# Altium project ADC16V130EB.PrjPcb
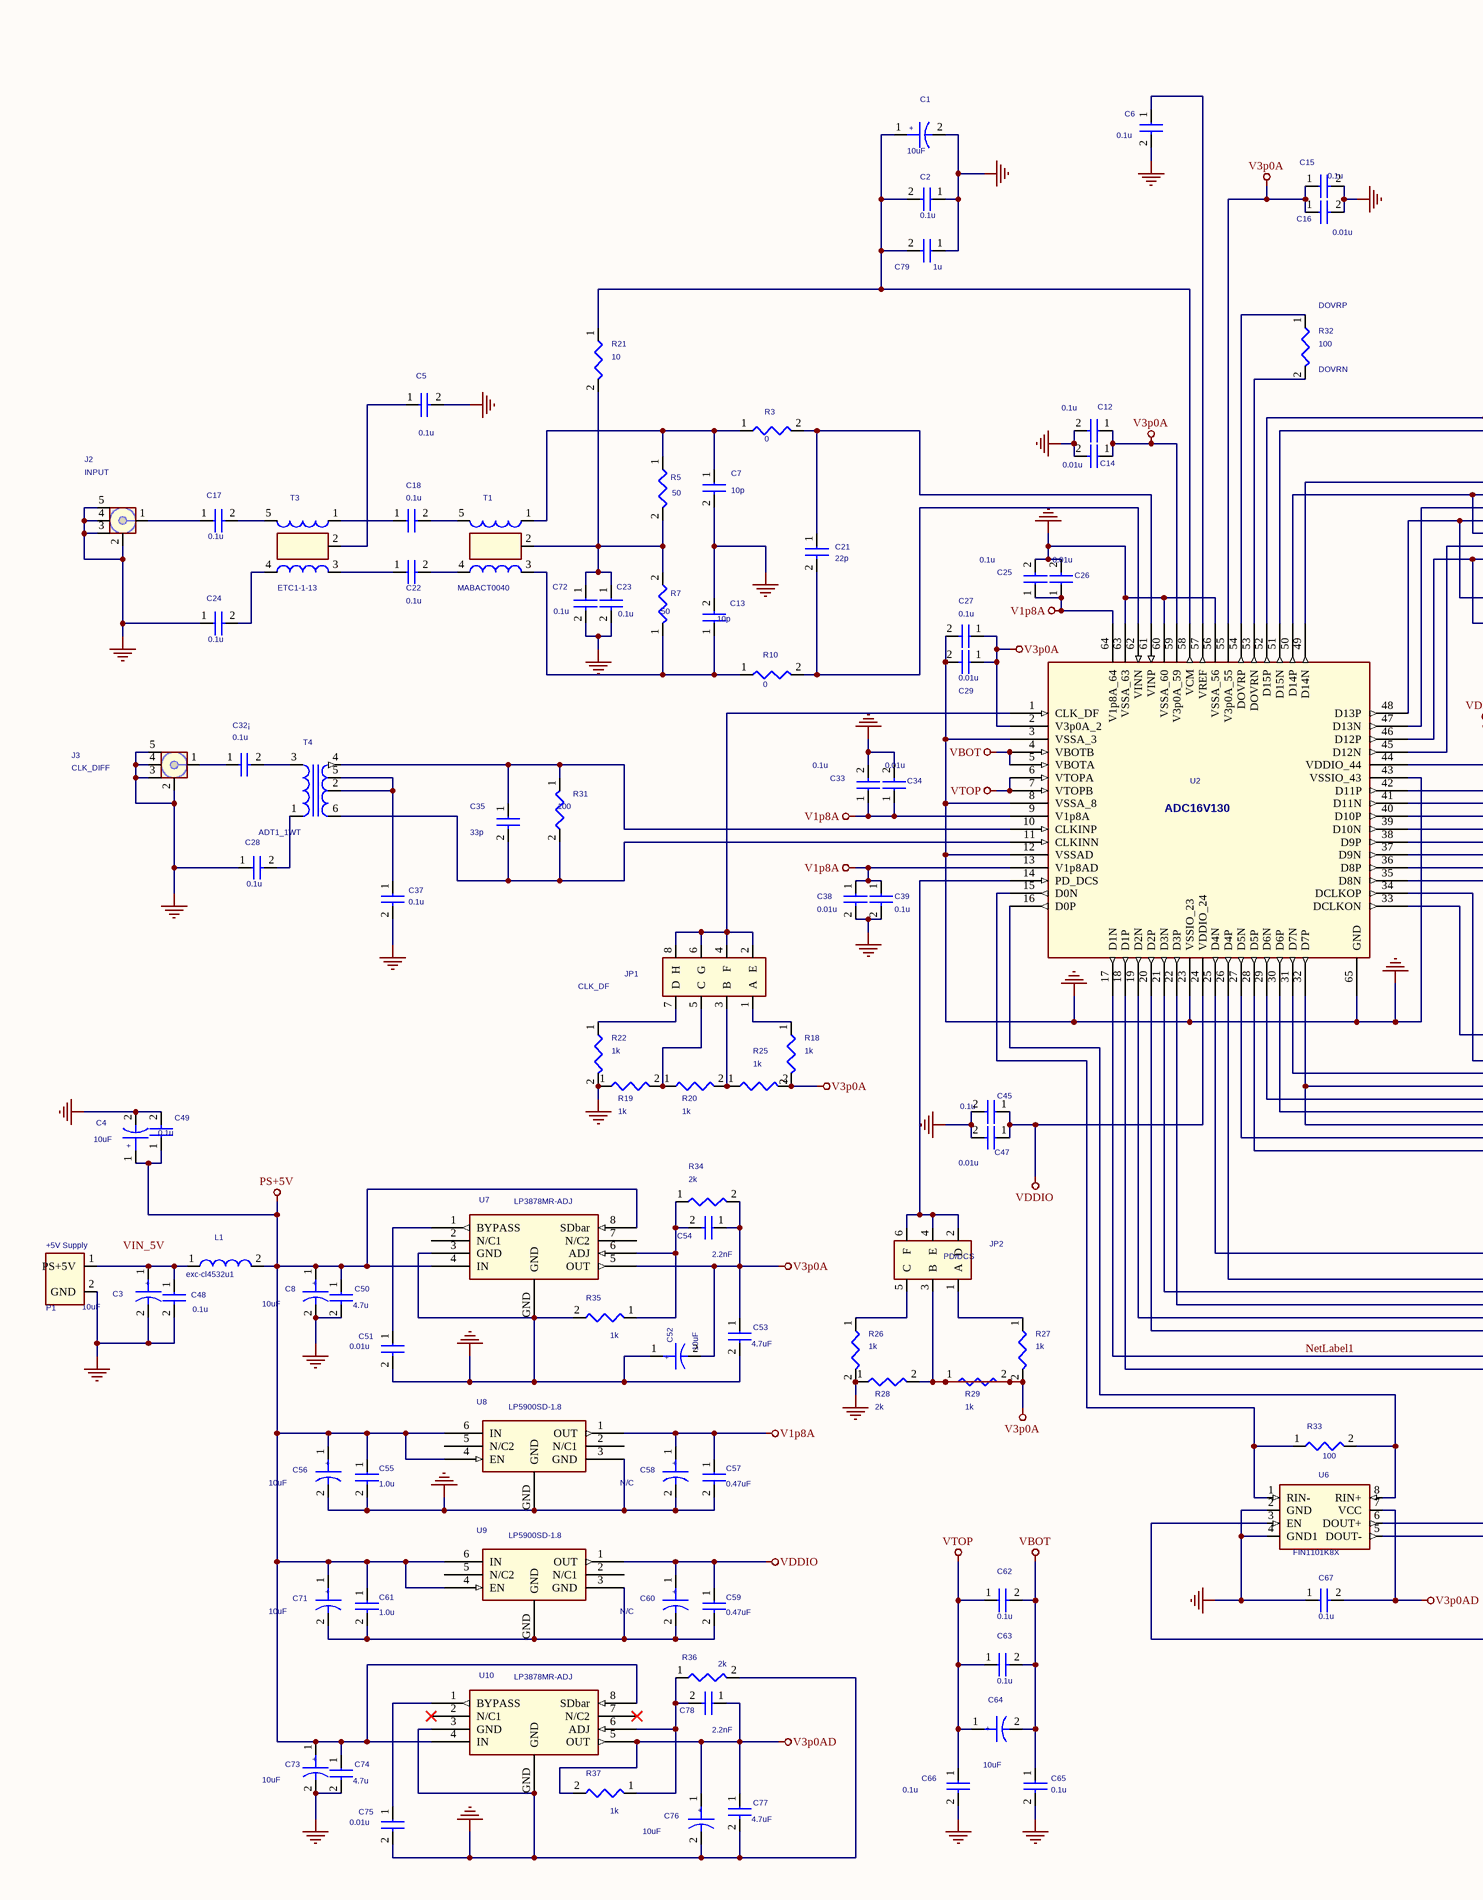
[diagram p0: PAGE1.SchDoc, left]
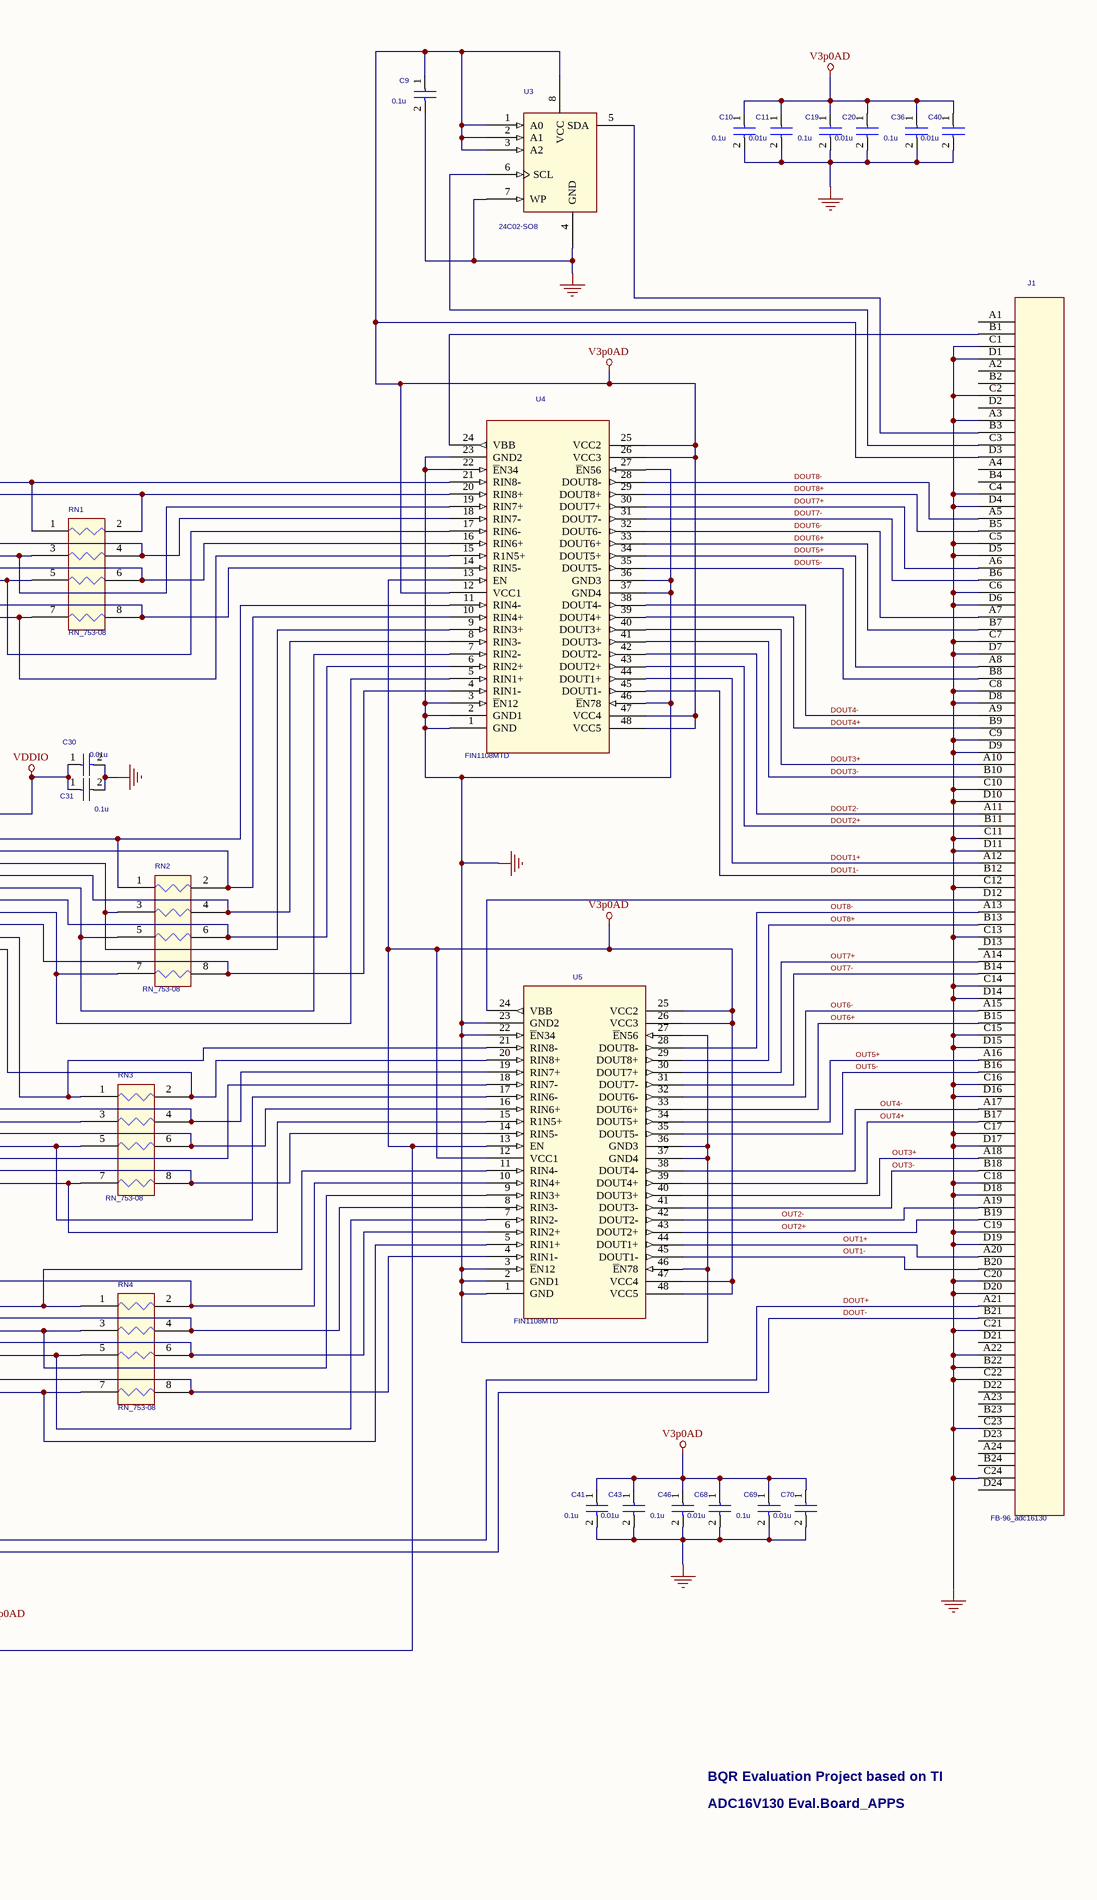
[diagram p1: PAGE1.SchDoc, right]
1 sheet, 121 parts. Net scope: global (net labels, ports and power ports of the same name join across sheets).

## Sheet PAGE1.SchDoc
size 513 x 386 mm

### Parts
C1  10uF  [cap_c-case]
C2  0.1u  [0201]
C3  10uF  [cap_c-case]
C4  10uF  [cap_c-case]
C5  0.1u  [0603]
C6  0.1u  [0402]
C7  10p  [0402]
C8  10uF  [cap_c-case]
C9  0.1u  [0603]
C10  0.1u  [0402]
C11  0.01u  [0402]
C12  0.1u  [0201]
C13  10p  [0402]
C14  0.01u  [0402]
C15  0.1u  [0201]
C16  0.01u  [0402]
C17  0.1u  [0603]
C18  0.1u  [0603]
C19  0.1u  [0402]
C20  0.01u  [0402]
C21  22p  [0402]
C22  0.1u  [0603]
C23  0.1u  [0603]
C24  0.1u  [0603]
C25  0.1u  [0201]
C26  0.01u  [0402]
C27  0.1u  [0402]
C28  0.1u  [0603]
C29  0.01u  [0402]
C30  0.01u  [0402]
C31  0.1u  [0402]
C32¡  0.1u  [0603]
C33  0.1u  [0402]
C34  0.01u  [0402]
C35  33p  [0402]
C36  0.1u  [0402]
C37  0.1u  [0603]
C38  0.01u  [0402]
C39  0.1u  [0402]
C40  0.01u  [0402]
C41  0.1u  [0402]
C43  0.01u  [0402]
C45  0.1u  [0402]
C46  0.1u  [0402]
C47  0.01u  [0402]
C48  0.1u  [0603]
C49  0.1u  [0603]
C50  4.7u  [0603]
C51  0.01u  [0603]
C52  10uF  [cap_c-case]
C53  4.7uF  [0603]
C54  2.2nF  [0603]
C55  1.0u  [0603]
C56  10uF  [cap_c-case]
C57  0.47uF  [0603]
C58  N/C  [cap_c-case]
C59  0.47uF  [0603]
C60  N/C  [cap_c-case]
C61  1.0u  [0603]
C62  0.1u  [0402]
C63  0.1u  [0402]
C64  10uF  [cap_a-case]
C65  0.1u  [0402]
C66  0.1u  [0402]
C67  0.1u  [0402]
C68  0.01u  [0402]
C69  0.1u  [0402]
C70  0.01u  [0402]
C71  10uF  [cap_c-case]
C72  0.1u  [0402]
C73  10uF  [cap_c-case]
C74  4.7u  [0603]
C75  0.01u  [0603]
C76  10uF  [cap_c-case]
C77  4.7uF  [0603]
C78  2.2nF  [0603]
C79  1u  [0508]
J1  FB-96_adc16130  [con96-fb_16130]
J2  INPUT  [RFSMAVCLRJ8]
J3  CLK_DIFF  [RFSMAVCLRJ8]
JP1  CLK_DF  [hdr-2x4-100]
JP2  PD/DCS  [hdr-2x3-100]
L1  exc-cl4532u1  [exc-cl4532u1]
P1  +5V Supply  [tb-2pos_plug]
R3  0  [0402]
R5  50  [0402]
R7  50  [0402]
R10  0  [0402]
R18  1k  [0603]
R19  1k  [0603]
R20  1k  [0603]
R21  10  [0603]
R22  1k  [0603]
R25  1k  [0603]
R26  1k  [0603]
R27  1k  [0603]
R28  2k  [0603]
R29  1k  [0603]
R31  100  [0402]
R32  100  [0402]
R33  100  [0402]
R34  2k  [0603]
R35  1k  [0603]
R36  2k  [0603]
R37  1k  [0603]
RN1  RN_753-08  [753083101gtr]
RN2  RN_753-08  [753083101gtr]
RN3  RN_753-08  [753083101gtr]
RN4  RN_753-08  [753083101gtr]
T1  MABACT0040  [etc1-1-13]
T3  ETC1-1-13  [etc1-1-13]
T4  ADT1_1WT  [ADT1]
U2  ADC16V130  [llp64_16130_no-skt]
U3  24C02-SO8  [soic8_150amps]
U4  FIN1108MTD  [tssop48_fin1108mtd]
U5  FIN1108MTD  [tssop48_fin1108mtd]
U6  FIN1101K8X  [us8_fin1101k8x]
U7  LP3878MR-ADJ  [lp3878-adj_mra08a-psop]
U8  LP5900SD-1.8  [lp5900_sdb06a-llp6]
U9  LP5900SD-1.8  [lp5900_sdb06a-llp6]
U10  LP3878MR-ADJ  [lp3878-adj_mra08a-psop]

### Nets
GND: C1.2 C2.1 C3.2 C4.2 C5.2 C6.2 C7.2 C8.2 C9.2 C10.2 C11.2 C12.2 C13.2 C14.2 C15.2 C16.2 C19.2 C20.2 C23.2 C24.1 C25.2 C26.2 C27.2 C28.1 C29.2 C30.2 C31.2 C33.2 C34.2 C36.2 C37.2 C38.2 C39.2 C40.2 C41.2 C43.2 C45.2 C46.2 C47.2 C48.2 C49.2 C50.2 C51.2 C52.1 C53.2 C55.2 C56.2 C57.2 C58.2 C65.2 C66.2 C67.1 C68.2 C69.2 C70.2 C72.2 C73.2 C74.2 C75.2 C76.2 C77.2 C79.1 J1.A3 J1.A22 J1.B22 J1.C1 J1.C2 J1.C4 J1.C5 J1.C6 J1.C7 J1.C8 J1.C9 J1.C10 J1.C11 J1.C12 J1.C13 J1.C14 J1.C15 J1.C16 J1.C17 J1.C18 J1.C19 J1.C20 J1.C21 J1.C22 J1.C23 J1.C24 J1.D1 J1.D4 J1.D5 J1.D6 J1.D7 J1.D8 J1.D9 J1.D10 J1.D11 J1.D14 J1.D15 J1.D16 J1.D17 J1.D18 J1.D19 J1.D20 J2.2(SHIELD2) J2.3(SHIELD3) J2.4(SHIELD4) J2.5(SHIELD5) J3.2(SHIELD2) J3.3(SHIELD3) J3.4(SHIELD4) J3.5(SHIELD5) P1.2(GND) R19.1 R22.2 R26.2 R28.1 R35.2 R36.2 U2.3(VSSA_3) U2.8(VSSA_8) U2.12(VSSAD) U2.23(VSSIO_23) U2.43(VSSIO_43) U2.56(VSSA_56) U2.60(VSSA_60) U2.63(VSSA_63) U2.65(GND) U3.4(GND) U3.7(WP) U4.1(GND) U4.2(GND1) U4.3(~{E}N12) U4.22(~{E}N34) U4.23(GND2) U4.27(~{E}N56) U4.36(GND3) U4.37(GND4) U4.46(~{E}N78) U5.1(GND) U5.2(GND1) U5.3(~{E}N12) U5.22(~{E}N34) U5.23(GND2) U5.27(~{E}N56) U5.36(GND3) U5.37(GND4) U5.46(~{E}N78) U6.2(GND) U6.4(GND1) U7.3(GND) U7.GND U8.3(GND) U8.GND U10.3(GND) U10.GND
PS+5V: C4.1 C8.1 C49.1 C50.1 C55.1 C56.1 C61.1 C71.1 C73.1 C74.1 L1.2 U7.4(IN) U7.8(SDbar) U8.4(EN) U8.6(IN) U9.4(EN) U9.6(IN) U10.4(IN) U10.8(SDbar)
V1p8A: C25.1 C26.1 C33.1 C34.1 C38.1 C39.1 C57.1 C58.1 U2.9(V1p8A) U2.13(V1p8AD) U2.64(V1p8A_64) U8.1(OUT)
V3p0A: C12.1 C14.1 C15.1 C16.1 C27.1 C29.1 C52.2 C53.1 C54.1 JP2.3(B) R18.2 R25.2 R27.2 R28.2 R29.1 R29.2 R34.2 U2.2(V3p0A_2) U2.55(V3p0A_55) U2.59(V3p0A_59) U7.5(OUT)
V3p0AD: C9.1 C10.1 C11.1 C19.1 C20.1 C36.1 C40.1 C41.1 C43.1 C46.1 C67.2 C68.1 C69.1 C70.1 C76.1 C77.1 C78.1 J1.D3 R37.2 U3.1(A0) U3.2(A1) U3.3(A2) U3.8(VCC) U4.12(VCC1) U4.13(EN) U4.25(VCC2) U4.26(VCC3) U4.47(VCC4) U4.48(VCC5) U5.12(VCC1) U5.13(EN) U5.25(VCC2) U5.26(VCC3) U5.47(VCC4) U5.48(VCC5) U6.3(EN) U6.7(VCC) U10.5(OUT)
VBOT: C62.2 C63.2 C64.2 C65.1 U2.4(VBOTB) U2.5(VBOTA)
VDDIO: C30.1 C31.1 C45.1 C47.1 C59.1 C60.1 U2.24(VDDIO_24) U2.44(VDDIO_44) U9.1(OUT)
VTOP: C62.1 C63.1 C64.1 C66.1 U2.6(VTOPA) U2.7(VTOPB)
DOUT1+: J1.A12 U4.44(DOUT1+)
DOUT1-: J1.B12 U4.45(DOUT1-)
DOUT2+: J1.B11 U4.43(DOUT2+)
DOUT2-: J1.A11 U4.42(DOUT2-)
DOUT3+: J1.A10 U4.40(DOUT3+)
DOUT3-: J1.B10 U4.41(DOUT3-)
DOUT4+: J1.B9 U4.39(DOUT4+)
DOUT4-: J1.A9 U4.38(DOUT4-)
DOUT5+: J1.A8 U4.34(DOUT5+)
DOUT5-: J1.B8 U4.35(DOUT5-)
DOUT6+: J1.B7 U4.33(DOUT6+)
DOUT6-: J1.A7 U4.32(DOUT6-)
DOUT7+: J1.A6 U4.30(DOUT7+)
DOUT7-: J1.B6 U4.31(DOUT7-)
DOUT8+: J1.B5 U4.29(DOUT8+)
DOUT8-: J1.A5 U4.28(DOUT8-)
DOUT+: J1.A21 U6.6(DOUT+)
DOUT-: J1.B21 U6.5(DOUT-)
NetLabel1: RN4.8 U2.17(D1N) U5.4(RIN1-)
OUT1+: J1.A20 U5.44(DOUT1+)
OUT1-: J1.B20 U5.45(DOUT1-)
OUT2+: J1.B19 U5.43(DOUT2+)
OUT2-: J1.A19 U5.42(DOUT2-)
OUT3+: J1.A18 U5.40(DOUT3+)
OUT3-: J1.B18 U5.41(DOUT3-)
OUT4+: J1.B17 U5.39(DOUT4+)
OUT4-: J1.A17 U5.38(DOUT4-)
OUT5+: J1.A16 U5.34(DOUT5+)
OUT5-: J1.B16 U5.35(DOUT5-)
OUT6+: J1.B15 U5.33(DOUT6+)
OUT6-: J1.A15 U5.32(DOUT6-)
OUT7+: J1.A14 U5.30(DOUT7+)
OUT7-: J1.B14 U5.31(DOUT7-)
OUT8+: J1.B13 U5.29(DOUT8+)
OUT8-: J1.A13 U5.28(DOUT8-)
NetC1_1: C1.1 C2.2 C79.2 R21.1 U2.58(VCM)
NetC3_1: C3.1 C48.1 L1.1 P1.1(PS+5V)
NetC5_1: C5.1 T3.2
NetC6_1: C6.1 U2.57(VREF)
NetC7_1: C7.1 R3.1 R5.1 T1.1
NetC13_1: C13.1 R7.1 R10.1 T1.3
NetC17_1: C17.1 J2.1(CENTER)
NetC17_2: C17.2 T3.5
NetC18_1: C18.1 T3.1
NetC18_2: C18.2 T1.5
NetC21_1: C21.1 R3.2 U2.61(VINP)
NetC21_2: C21.2 R10.2 U2.62(VINN)
NetC22_1: C22.1 T3.3
NetC22_2: C22.2 T1.4
NetC23_1: C23.1 C72.1 R5.2 R7.2 R21.2 T1.2
NetC24_2: C24.2 T3.4
NetC28_2: C28.2 T4.1
NetC32¡_1: C32¡.1 J3.1(CENTER)
NetC32¡_2: C32¡.2 T4.3
NetC35_1: C35.1 R31.1 T4.4 U2.10(CLKINP)
NetC35_2: C35.2 R31.2 T4.6 U2.11(CLKINN)
NetC37_1: C37.1 T4.2 T4.5
NetC51_1: C51.1 U7.1(BYPASS)
NetC54_2: C54.2 R34.1 R35.1 U7.6(ADJ)
NetC59_2: C59.2 C60.2 C61.2 C71.2 U9.3(GND) U9.GND
NetC75_1: C75.1 U10.1(BYPASS)
NetC78_2: C78.2 R36.1 R37.1 U10.6(ADJ)
NetJ1_B1: J1.B1 U4.24(VBB)
NetJ1_B3: J1.B3 U3.5(SDA)
NetJ1_C3: J1.C3 U3.6(SCL)
NetJ1_D12: J1.D12 U5.24(VBB)
NetJP1_1: JP1.1(A) R18.1
NetJP1_2: JP1.2(E) JP1.4(F) JP1.6(G) JP1.8(H) U2.1(CLK_DF)
NetJP1_3: JP1.3(B) R20.2 R25.1
NetJP1_5: JP1.5(C) R19.2 R20.1
NetJP1_7: JP1.7(D) R22.1
NetJP2_1: JP2.1(A) R27.1
NetJP2_2: JP2.2(D) JP2.4(E) JP2.6(F) U2.14(PD_DCS)
NetJP2_5: JP2.5(C) R26.1
NetR32_1: R32.1 U2.54(DOVRP)
NetR32_2: R32.2 U2.53(DOVRN)
NetR33_1: R33.1 U2.15(D0N) U6.1(RIN-)
NetR33_2: R33.2 U2.16(D0P) U6.8(RIN+)
NetRN1_1: RN1.1 U2.52(D15P) U4.21(RIN8-)
NetRN1_2: RN1.2 U2.51(D15N) U4.20(RIN8+)
NetRN1_3: RN1.3 U2.50(D14P) U4.19(RIN7+)
NetRN1_4: RN1.4 U2.49(D14N) U4.18(RIN7-)
NetRN1_5: RN1.5 U2.48(D13P) U4.17(RIN6-)
NetRN1_6: RN1.6 U2.47(D13N) U4.16(RIN6+)
NetRN1_7: RN1.7 U2.46(D12P) U4.15(R1N5+)
NetRN1_8: RN1.8 U2.45(D12N) U4.14(RIN5-)
NetRN2_1: RN2.1 U2.42(D11P) U4.11(RIN4-)
NetRN2_2: RN2.2 U2.41(D11N) U4.10(RIN4+)
NetRN2_3: RN2.3 U2.40(D10P) U4.9(RIN3+)
NetRN2_4: RN2.4 U2.39(D10N) U4.8(RIN3-)
NetRN2_5: RN2.5 U2.38(D9P) U4.7(RIN2-)
NetRN2_6: RN2.6 U2.37(D9N) U4.6(RIN2+)
NetRN2_7: RN2.7 U2.36(D8P) U4.5(RIN1+)
NetRN2_8: RN2.8 U2.35(D8N) U4.4(RIN1-)
NetRN3_1: RN3.1 U2.34(DCLKOP) U5.21(RIN8-)
NetRN3_2: RN3.2 U2.33(DCLKON) U5.20(RIN8+)
NetRN3_3: RN3.3 U2.32(D7P) U5.18(RIN7-)
NetRN3_4: RN3.4 U2.31(D7N) U5.19(RIN7+)
NetRN3_5: RN3.5 U2.30(D6P) U5.17(RIN6-)
NetRN3_6: RN3.6 U2.29(D6N) U5.16(RIN6+)
NetRN3_7: RN3.7 U2.28(D5P) U5.15(R1N5+)
NetRN3_8: RN3.8 U2.27(D5N) U5.14(RIN5-)
NetRN4_1: RN4.1 U2.26(D4P) U5.11(RIN4-)
NetRN4_2: RN4.2 U2.25(D4N) U5.10(RIN4+)
NetRN4_3: RN4.3 U2.22(D3P) U5.9(RIN3+)
NetRN4_4: RN4.4 U2.21(D3N) U5.8(RIN3-)
NetRN4_5: RN4.5 U2.20(D2P) U5.7(RIN2-)
NetRN4_6: RN4.6 U2.19(D2N) U5.6(RIN2+)
NetRN4_7: RN4.7 U2.18(D1P) U5.5(RIN1+)

Not connected (* = marked no-connect by the designer): J1 A1(1) A2(5) A4(13) A23(89) A24(93) B2(6) B4(14) B23(90) B24(94) D2(8) D13(52) D21(84) D22(88) D23(92) D24(96); U7 2(N/C1) 7(N/C2); U8 2(N/C1) 5(N/C2); U9 2(N/C1) 5(N/C2); U10 2(N/C1)* 7(N/C2)*

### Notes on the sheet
- (near R32) DOVRP
- (near R32) DOVRN
- BQR Evaluation Project based on TI
- ADC16V130 Eval.Board_APPS
- Labels drawn without touching a wire or pin: VIN_5V

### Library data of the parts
C1 C4 C8 C52 C56 C58 C60 C71 C73 = Cap_Polar_1: CAP TANT 10UF 20V 10% 2312; Manufacturer P/N: TAJC106K020R; Manufacturer: AVX; Catalog Number: CAP00001
C2 = Capacitor_4: CAP CER 0.1UF 6.3V X5R 0201; Manufacturer P/N: GRM033R60J104KE19D; Manufacturer: Murata; Catalog Number: CAP00002
C3 = Cap_Polar_1: CAP TANT 10UF 6.3V 10% 1206; Manufacturer: AVX_1; Manufacturer P/N: TAJA106K006R; Catalog Number: CAP00039
C5 C17 C18 C22-C24 C28 C32¡ C37 = Capacitor_4: CAP CER 0.1UF 16V X7R 0603; Manufacturer: Murata; Manufacturer P/N: GRM188R71C104KA01D; Catalog Number: CAP00036
C6 C65 C66 C72 = Capacitor_4: CAP CER 0.1UF 10V X5R 0402; Manufacturer P/N: GRM155R61A104KA01D; Manufacturer: Murata; Catalog Number: CAP00026
C7 = Capacitor_4: CAP CER 10PF 50V NP0 0402; Manufacturer: Murata; Manufacturer P/N: GRM1555C1H100JZ01D; Catalog Number: CAP00029
C9 = Capacitor_4: CAP CER 0.1UF 16V X7R 0603; Manufacturer: Murata; Manufacturer P/N: GRM188R71C104KA01D; Catalog Number: CAP00036; SDTA_V(Voltage): 3
C10 C19 C36 C41 C46 C69 = Capacitor_4: CAP CER 0.1UF 10V X5R 0402; Manufacturer P/N: GRM155R61A104KA01D; Manufacturer: Murata; Catalog Number: CAP00026; SDTA_V(Voltage): 3
C11 C20 C40 C43 C68 C70 = Capacitor_4: CAP CER 10000PF 50V X7R 0402; Manufacturer P/N: GRM155R71H103KA88D; Manufacturer: Murata; Catalog Number: CAP00027; SDTA_V(Voltage): 3
C12 C15 C25 = Cap_1: CAP CER 0.1UF 6.3V X5R 0201; Manufacturer P/N: GRM033R60J104KE19D; Manufacturer: Murata; Catalog Number: CAP00002
C13 = Capacitor_4: CAP CER 10PF 50V NP0 0402; Manufacturer P/N: GRM1555C1H100JZ01D; Manufacturer: Murata; Catalog Number: CAP00029
C14 C16 C26 C29 C30 C34 C38 C47 = Cap_1: CAP CER 10000PF 50V X7R 0402; Manufacturer P/N: GRM155R71H103KA88D; Manufacturer: Murata; Catalog Number: CAP00027
C21 = Capacitor_4: CAP CER 22PF 50V NP0 0402; Manufacturer P/N: GRM1555C1H220JZ01D; Manufacturer: Murata; Catalog Number: CAP00037
C27 C31 C33 C39 C45 = Cap_1: CAP CER 0.1UF 10V X5R 0402; Manufacturer P/N: GRM155R61A104KA01D; Manufacturer: Murata; Catalog Number: CAP00026
C35 = Capacitor_3: CAP CER 33PF 50V NP0 0402; Manufacturer: Murata; Manufacturer P/N: GRM1555C1H330JZ01D; Catalog Number: CAP00038
C48 C49 = Capacitor_3: CAP CER 0.1UF 16V X7R 0603; Manufacturer: Murata; Manufacturer P/N: GRM188R71C104KA01D; Catalog Number: CAP00036
C50 = Capacitor_3: CAP CER 4.7UF 6.3V X5R 0603; Manufacturer: Panasonic; Manufacturer P/N: ECJ-1VB0J475M; Catalog Number: CAP00017
C51 C75 = Capacitor_3: CAP CER 10000PF 50V X7R 0603; Manufacturer P/N: ECJ-1VB1H103K; Manufacturer: Panasonic; Catalog Number: CAP00018
C53 C74 = Capacitor_3: CAP CER 4.7UF 6.3V X5R 0603; Manufacturer P/N: ECJ-1VB0J475M; Manufacturer: Panasonic; Catalog Number: CAP00017
C54 C78 = Cap_1: CAP CER 2200PF 50V X7R 0603; Manufacturer P/N: ECJ-1VB1H222K; Manufacturer: Panasonic; Catalog Number: CAP00019
C55 = Capacitor_3: CAP CER 1UF 16V X7R 0603; Manufacturer: Murata; Manufacturer P/N: GRM188R71C105KA12D; Catalog Number: CAP00028
C57 C59 = Capacitor_3: CAP CER 0.47UF 6.3V X5R 0603; Manufacturer P/N: ECJ-1VB0J474K; Manufacturer: Panasonic; Catalog Number: CAP00016
C61 = Capacitor_3: CAP CER 1UF 16V X7R 0603; Manufacturer P/N: GRM188R71C105KA12D; Manufacturer: Murata; Catalog Number: CAP00028
C62 C63 = Capacitor_3: CAP CER 0.1UF 10V X5R 0402; Manufacturer P/N: GRM155R61A104KA01D; Manufacturer: Murata; Catalog Number: CAP00026
C64 = Cap_Polar_1: CAP TANT 10UF 10V 20% 1206; Manufacturer P/N: F931A106MAA; Manufacturer: Nichicon; Catalog Number: CAP00023
C67 = Cap_1: CAP CER 0.1UF 10V X5R 0402; Manufacturer P/N: GRM155R61A104KA01D; Manufacturer: Murata; Catalog Number: CAP00026; SDTA_V(Voltage): 3
C76 = Cap_Polar_1: CAP TANT 10UF 20V 10% 2312; Manufacturer P/N: TAJC106K020R; Manufacturer: AVX; Catalog Number: CAP00001; SDTA_V(Voltage): 3
C77 = Capacitor_3: CAP CER 4.7UF 6.3V X5R 0603; Manufacturer: Panasonic; Manufacturer P/N: ECJ-1VB0J475M; Catalog Number: CAP00017; SDTA_V(Voltage): 3
C79 = Capacitor_4: CAP CER 1UF 10V X5R 0508; Manufacturer P/N: ECY-29RA105KV; Manufacturer: Panasonic; Catalog Number: CAP00020
J1 = CON-FB96-ADC16130: 2MM FB,IS,ASY,024,SIG,HDR,SL; Manufacturer: AMP/Tyco; Manufacturer P/N: 223514-1; Catalog Number: CON00005
J2 = SMA_CONN_4: SMA Connector Jack, Female Socket 50 Ohm Board Edge, End Launch Solder Tab; Manufacturer: JOHNSON; Manufacturer P/N: 142-0701-851; Catalog Number: CON00004
J3 = SMA_CONN_5: SMA Connector Jack, Female Socket 50 Ohm Board Edge, End Launch Solder Tab; Manufacturer P/N: 142-0701-851; Manufacturer: JOHNSON; Catalog Number: CON00004
JP1 = HDR-2x4_0: 8 Positions Header, Unshrouded Connector 0.100" (2.54mm) Through Hole Gold; Manufacturer P/N: TSW-104-07-F-D; Manufacturer: Samtec; Catalog Number: CON00035
JP2 = HDR-2x3: 6 Positions Header, Unshrouded Connector 0.100" (2.54mm) Through Hole Gold; Manufacturer P/N: TSW-103-07-F-D; Manufacturer: Samtec; Catalog Number: CON00034
L1 = Inductor: FERRITE BEAD 115 OHM 1812 1LN; Manufacturer: Panasonic; Catalog Number: IND00022
P1 = TB2_1: CONN RCPT SUR 2POS .8MM TIN; Manufacturer P/N: 02SUR-32S; Manufacturer: JST; Catalog Number: CON00003
R3 R10 = Resistor_3: RES SMD 0.0OHM JUMPER 1/16W 0402; Manufacturer: Vishay; Manufacturer P/N: CRCW04020000Z0ED; Catalog Number: RES00015
R5 R7 = Resistor_3: RES SMD 49.9 OHM 1% 1/16W 0402; Manufacturer P/N: CRCW040249R9FKED; Manufacturer: Vishay; Catalog Number: RES00012
R18-R20 R22 R25-R27 R29 R35 R37 = Resistor_3: RES SMD 1K OHM 1% 1/10W 0603; Manufacturer P/N: CRCW06031K00FKEA; Manufacturer: Vishay; Catalog Number: RES00010
R21 = Resistor_3: RES SMD 10 OHM 1% 1/10W 0603; Manufacturer P/N: CRCW060310R0FKEA; Manufacturer: Vishay; Catalog Number: RES00013
R28 R34 R36 = Resistor_3: RES SMD 2K OHM 1% 1/10W 0603; Manufacturer P/N: CRCW06032K00FKEA; Manufacturer: Vishay; Catalog Number: RES00011
R31 R33 = Resistor_3: RES SMD 100 OHM 1% 1/16W 0402; Manufacturer P/N: CRCW0402100RFKED; Manufacturer: Vishay; Catalog Number: RES00014
R32 = Resistor_3: RES SMD 100 OHM 1% 1/16W 0402; Manufacturer: Vishay; Manufacturer P/N: CRCW0402100RFKED; Catalog Number: RES00014
RN1-RN4 = RN_753-08: RES ARRAY 4 RES 100 OHM 8SRT; Manufacturer: CTS; Catalog Number: RES00006
T1 = ETC1-1-13: Transformers Audio & Signal 5-1000MHz IL 1.1dB Ctr Tap -40C +85C; Manufacturer: MA-COM; Catalog Number: IND00032
T3 = ETC1-1-13: TRANSFORMER; Manufacturer: MA-COM; Catalog Number: IND00021
T4 = ADT1_2: RF TRANSF 75 OHM 0.4-800 MHz; Manufacturer: Mini-Circuits; Catalog Number: IND00008
U2 = ADC16130_LLP_13: IC ADC 16BIT 130MSPS LVDS 64WQFN; Manufacturer P/N: ADC16V130CISQE/NOPB; Manufacturer: Texas Instruments; Catalog Number: IC00007
U3 = 24C02-SO8_2: EEPROM 2/4/8/16K 2-WIRE BUS; Manufacturer: Atmel; Manufacturer P/N: AT24C02AN-10SU-2.7; Catalog Number: IC00009
U4 U5 = FIN1108MTD_1: IC REDRIVER LVDS 8CH 48TSSOP; Manufacturer: Fairchild; Catalog Number: IC00025
U6 = FIN1101K8X_0: IC REDRIVER LVDS 1CH 1.6GBPS US8; Manufacturer: Fairchild; Catalog Number: IC00024
U7 = LP3878MR-ADJ_4: Linear Voltage Regulator IC Positive Adjustable 1 Output 1 V ~ 5.5 V 800mA 8-SO PowerPad; Manufacturer: Texas Instruments; Manufacturer P/N: LP3878MR-ADJ/NOPB; Catalog Number: IC00030
U8 U9 = LP5900SD-1_0.8: IC REG LDO 1.8V 0.15A 6WSON; Manufacturer: Texas Instruments; Manufacturer P/N: LP5900SD-1.8/NOPB; Catalog Number: IC00031
U10 = LP3878MR-ADJ_5: Linear Voltage Regulator IC Positive Adjustable 1 Output 1 V ~ 5.5 V 800mA 8-SO PowerPad; Manufacturer P/N: LP3878MR-ADJ/NOPB; Manufacturer: Texas Instruments; Catalog Number: IC00030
